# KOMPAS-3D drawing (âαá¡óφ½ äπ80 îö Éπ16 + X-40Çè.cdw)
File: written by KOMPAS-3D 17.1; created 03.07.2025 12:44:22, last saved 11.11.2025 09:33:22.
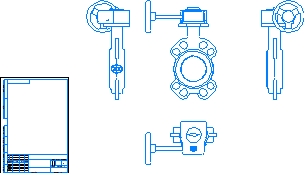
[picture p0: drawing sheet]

Sheet 1: A4, portrait

Title block, sheet 1: sheets: 1; sheet format: A4; stored path: \\adlc.lan\data\АДЛ_ПКД\3D-модели\ADL production\Дисковые поворотные затворы ГРАНВЭЛ\межфланцевый с китайским редуктором Ру16\KOMPAS 2D\Гранвэл Ду80 МФ Ру16 + X-40АК.cdw

Views: Вид 1, Спереди, Проекционный вид 2, Проекционный вид 3, Проекционный вид 4
Referenced files in \\adlc.lan\data\АДЛ_ПКД\3D-модели\ADL production\Дисковые поворотные затворы ГРАНВЭЛ\межфланцевый с китайским редуктором Ру16\KOMPAS 3D\: Гранвэл Ду80 МФ Ру16 + X-40АК.m3d
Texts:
  Andrey
  АДЛ
Dimensions and other numbers on the sheet: 1:1; 1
